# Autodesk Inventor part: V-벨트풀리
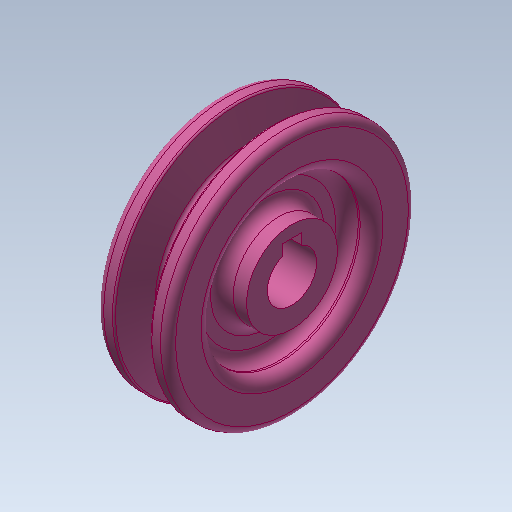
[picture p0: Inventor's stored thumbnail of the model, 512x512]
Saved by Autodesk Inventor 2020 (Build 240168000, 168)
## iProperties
Created: 2015-12
Part Number: V-벨트풀리
Material: 강철, 연강
Document SubType Name: Modeling
Designer: mduedu
Density: 7.86 g/cm^3
Appearance: 분홍색
Author: mduedu
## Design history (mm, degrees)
sketch "스케치1"
  geometry: L1 (-9.5, 0)-(9.5, 0); L2 (-9.5, 0)-(-9.5, 32.7); L3 (-9.5, 32.7)-(-4.825, 32.7); L4 (-4.825, 32.7)-(-2.074, 23.7); L5 (-2.074, 23.7)-(0, 23.7); L6 (0, 0)-(0, 23.7); L7 (9.5, 0)-(9.5, 32.7); L8 (9.5, 32.7)-(4.825, 32.7); L9 (4.825, 32.7)-(2.074, 23.7); L10 (2.074, 23.7)-(0, 23.7); L11 (-4, 30)-(4, 30); 3 further points
  constraints: 22 end point, 3 coincident, 3 perpendicular, 3 symmetric about line, 2 parallel, 2 point on line, 1 horizontal, 1 midpoint, 1 vertical alignment
  dimensions: "d0" = 19 distance between parallel lines of L7 L2; "d2" = 6.3 distance between parallel lines of L10 L11; "d3" = 34 deg angle of L9 L4; "d4" = 2.7 distance between parallel lines of L11 L8; "d5" = 60 diameter of L11 L1; "d6" = 8 distance of L11.end L11.start
revolve "회전1" sketch "스케치1" stored, may be unused: angle "d7" = 90 deg
sketch "스케치2"
  geometry: C1 r 21 at (0, 0); C2 r 12 at (0, 0); 1 further point
  constraints: 2 centre point, 2 coincident
  dimensions: "d8" = 42 diameter of C1; "d10" = 24 diameter of C2
extrude "돌출1" cut sketch "스케치2" distance "d11" = 6.5; taper "d12" = 0 deg
fillet "모깎기1" dims "d13" = 1, "d14" = 0.5, "d15" = 2
fillet "모깎기2" dims "d16" = 3
fillet "모깎기3" dims "d17" = 3
hole "구멍1" diameter "d20" = 13; stored, may be unused: countersink angle "d24" = 90 deg, drill point angle "d26" = 118 deg; dims "d18" = 10, "d19" = 10, "d21" = 6, "d22" = 4, "d23" = 2, "d25" = 8
sketch "스케치3"
  geometry: L1 (-2.5, 0)-(2.5, 0); L2 (2.5, 0)-(2.5, 8.8); L3 (2.5, 8.8)-(-2.5, 8.8); L4 (-2.5, 8.8)-(-2.5, 0); 2 further points
  constraints: 8 end point, 2 parallel, 1 coincident, 1 horizontal, 1 midpoint, 1 perpendicular
  dimensions: "d27" = 8.8 distance of L1.end L2.end; "d29" = 5 distance of L2.end L3.end
extrude "돌출2" cut sketch "스케치3" extent not by distance; stored distance "d30" = 6.5; taper "d31" = 0 deg
node "솔리드1"
mirror "대칭1"
